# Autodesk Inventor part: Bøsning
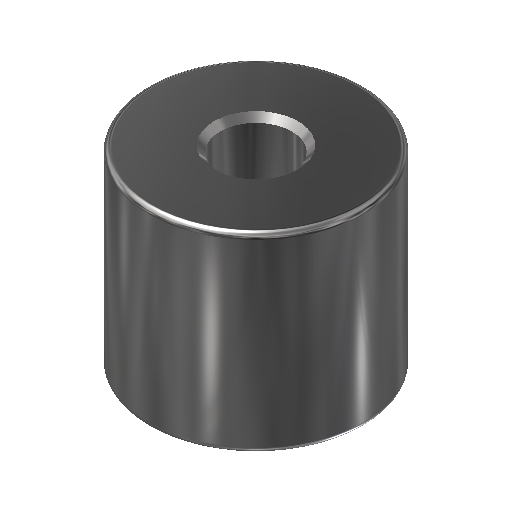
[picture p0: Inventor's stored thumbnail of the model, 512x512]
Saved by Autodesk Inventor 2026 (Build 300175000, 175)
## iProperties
Created: 2013-10
Part Number: Bøsning
Material: Steel, Mild
Document SubType Name: Modeling
Designer: Lars Bertram Pedersen
Density: 7.85 g/cm^3
Appearance: Semi-Polished
Mass: 28.324 g
Surface Area: 16.2388 cm^2
Volume: 3.60815 cm^3
Stock Number: 2003
Author: Lars Bertram Pedersen
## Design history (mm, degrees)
revolve "Revolution1" stored, may be unused: angle "d2" = 90 deg
hole "Hole1" diameter "d5" = 6; stored, may be unused: countersink angle "d9" = 90 deg, drill point angle "d11" = 118 deg; dims "d6" = 6, "d7" = 4, "d8" = 2, "d10" = 8, "d14" = 10, "d15" = 10
fillet "Fillet1" dims "d12" = 0.5
chamfer "Chamfer1" distance "d13" = 0.5; stored, may be unused: second distance "d16" = 2, angle "d17" = 45 deg
body "Solid1"
sketch "Sketch1"
  geometry: L1 (0, 0)-(0, 16); L2 (0, 16)-(9, 16); L3 (9, 16)-(9, 0); L4 (9, 0)-(0, 0); L5 (0, 16)-(0, 0)
  constraints: 10 end point, 3 equal length, 1 perpendicular, 1 vertical
  dimensions: "d0" = 18 diameter of L3 L1; "d1" = 16 distance between parallel lines of L4 L2
